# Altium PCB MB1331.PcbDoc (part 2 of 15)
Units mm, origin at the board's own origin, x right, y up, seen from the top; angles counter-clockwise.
Board outline 169.25 x 173.25 mm, 6 copper layers (Top Layer, Signal Layer 1, Signal Layer 2, Signal Layer 3, Signal Layer 4, Bottom Layer), stack 1.556 mm thick; 871 components, 699 nets, 3244 pads, 2370 vias.
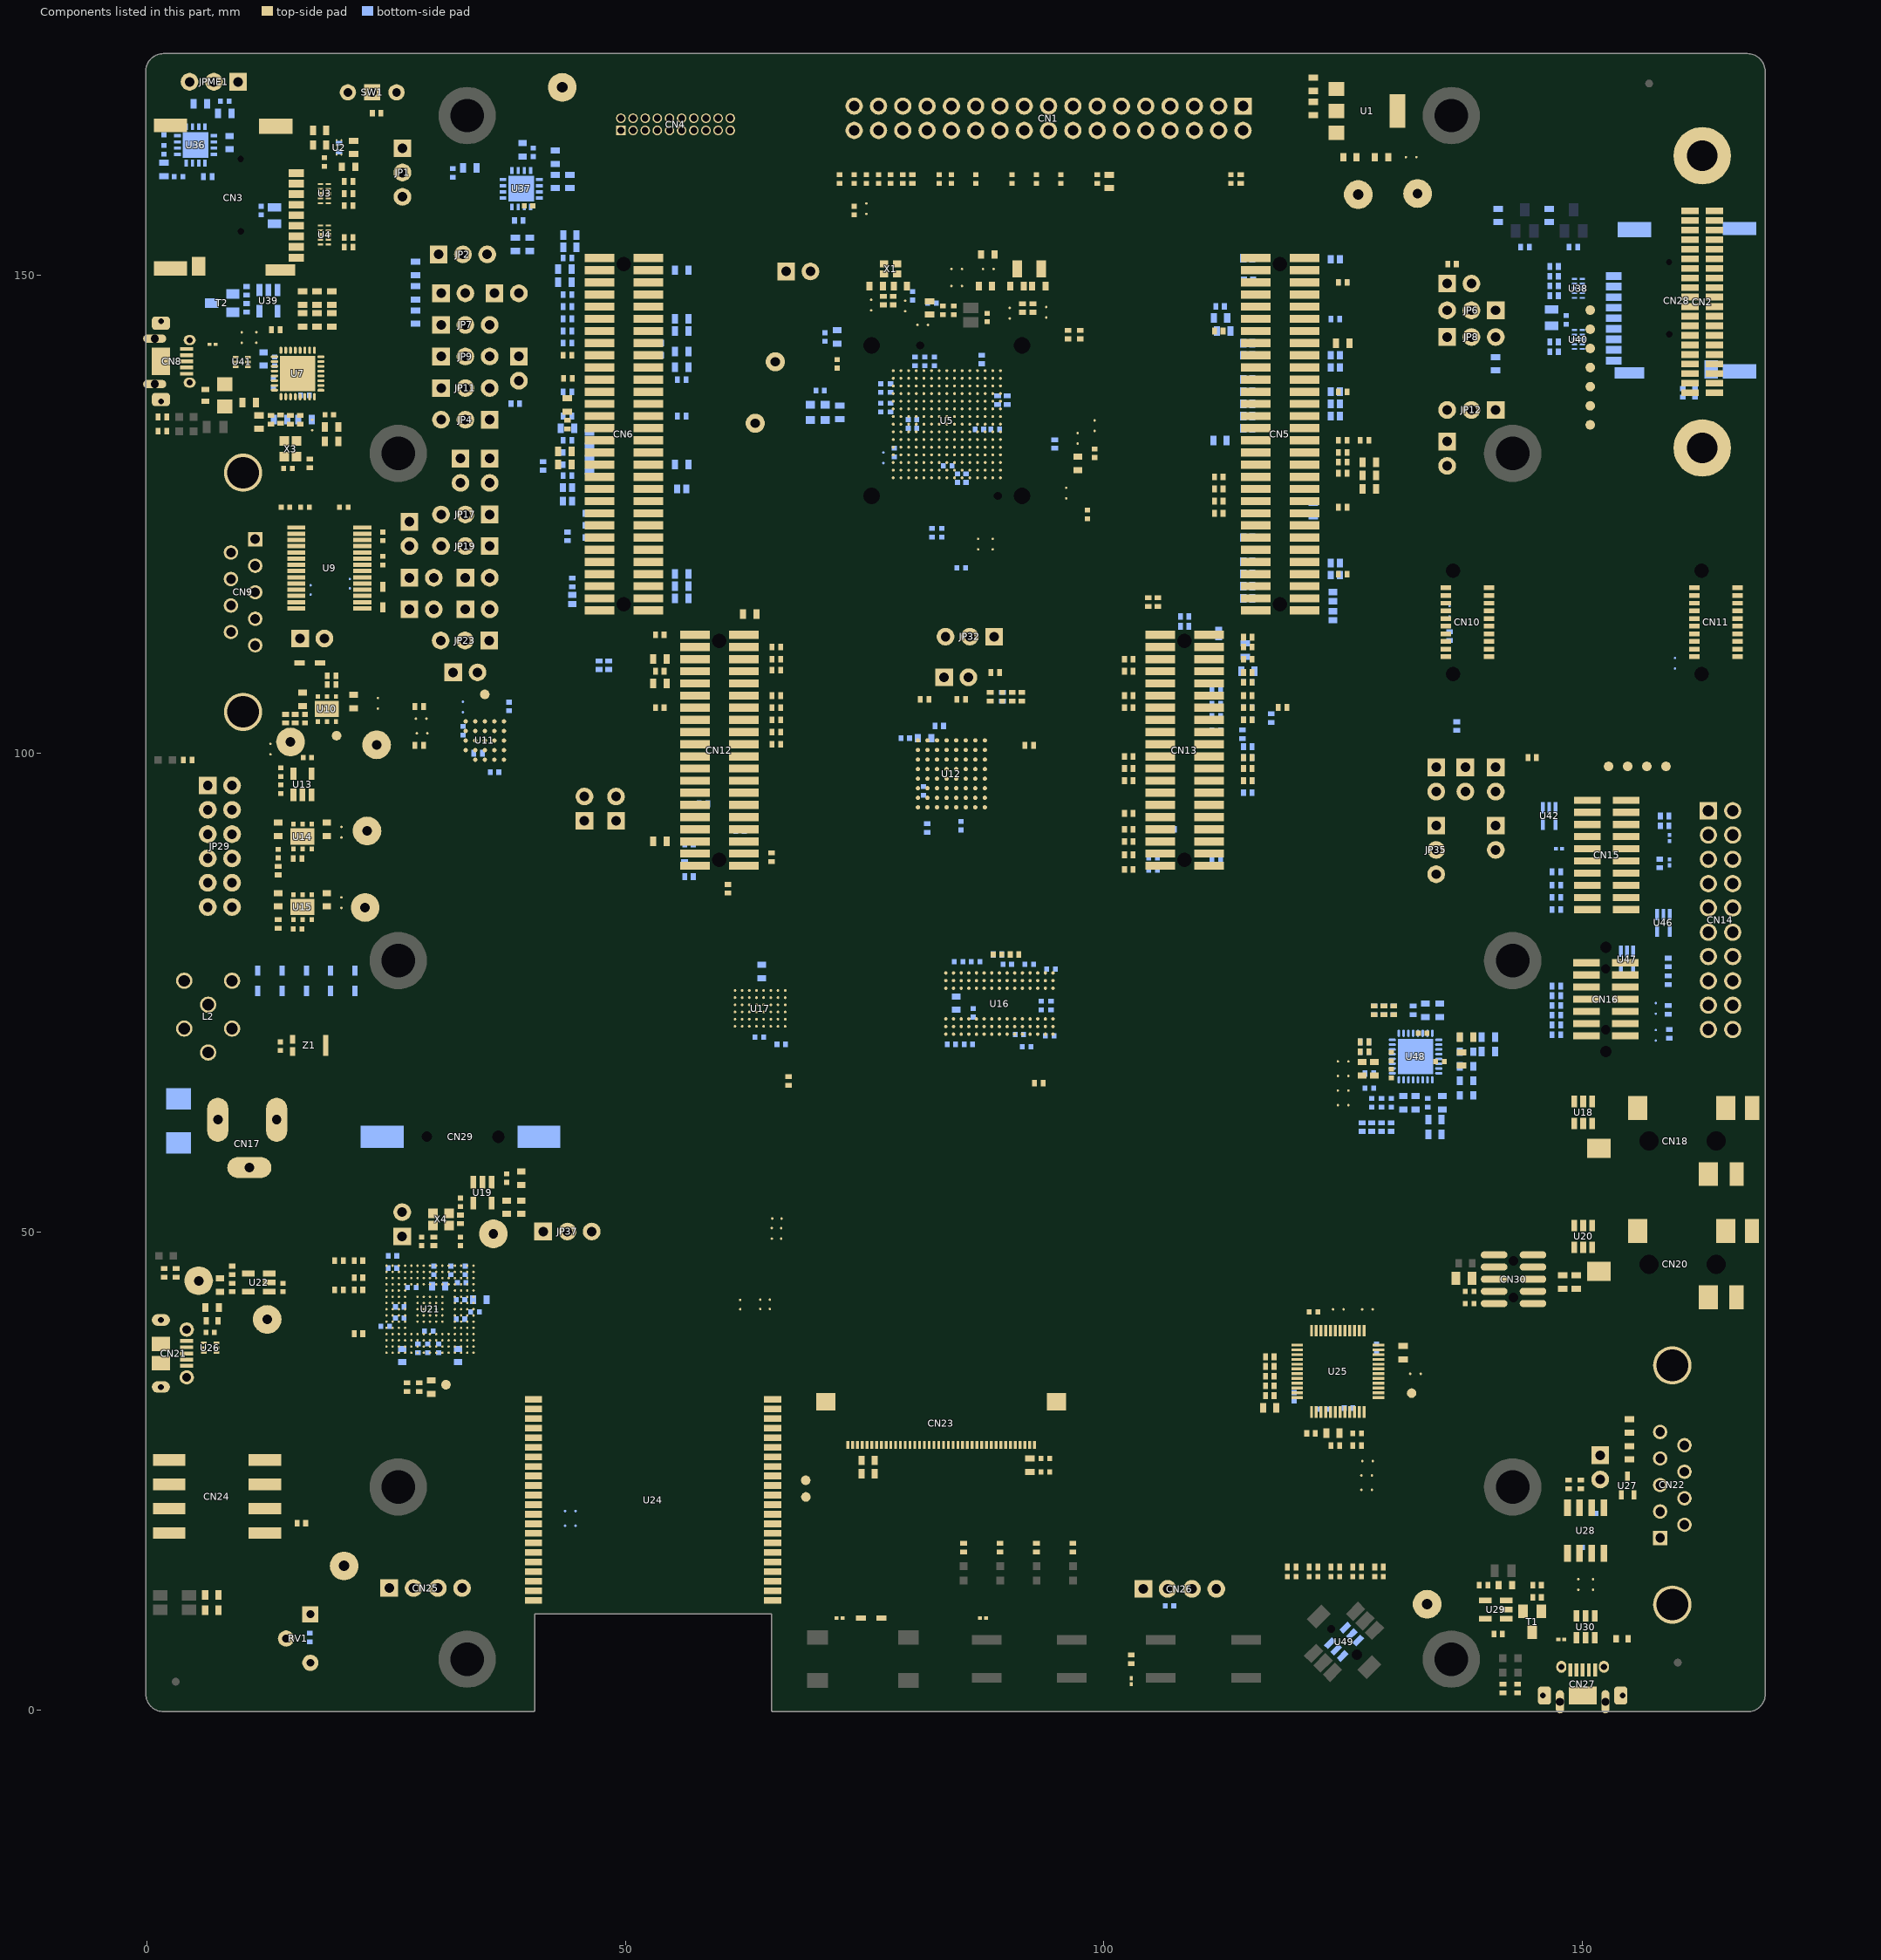
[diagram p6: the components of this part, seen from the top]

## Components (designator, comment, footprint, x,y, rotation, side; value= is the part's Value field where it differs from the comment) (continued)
R185 "Resistor" R0402 124.206,14.986 r0 top value=10K
R186 "Resistor" R0402 126.492,14.986 r180 top value=10K
R187 "Resistor" R0402 128.778,14.986 r0 top value=10K
R188 "Resistor" R0402 139.7,13.081 r0 top value=10K
R189 "Resistor" R0402 145.288,13.081 r0 top value=47K
R190 "Resistor" R0603 6.777,12.078 r0 top value=330R
R191 "Resistor" R0402 145.288,11.811 r0 top value=10K
R192 "Resistor" R0603 6.777,10.478 r0 top value=330R
R193 "Resistor" R0402 141.224,8.001 r180 top value=47K
R194 "Resistor" R0402 102.87,5.334 r90 top value=10K
R195 "Resistor" R0402 141.732,2.286 r270 top value=360R
R196 "Resistor" R0402 143.256,2.286 r270 top value=270R
R197 "Resistor" R0603 5.588,167.894 r180 bottom value=1K
R198 "Resistor" R0603 8.128,166.878 r180 bottom value=1K
R199 "Resistor" R0402 20.066,163.322 r270 bottom value=10K
R200 "PT100" R0603_H0P45 42.672,162.306 r270 bottom value="PTS 100R @ 0°C"
R201 "Resistor" R0603 33.738,161.163 r180 bottom value=0R
R202 "Resistor" R0603 1.778,161.036 r270 bottom value=0R
R203 "Resistor" R0603 44.196,159.766 r90 bottom value=3K3
R204 "Resistor" R0603 42.672,159.766 r270 bottom value=100R
R205 "Resistor" R0402 6.35,160.274 r0 bottom value=0R
R206 "Resistor" R0603 146.558,156.21 r270 bottom value=0R
R207 "Resistor" R0603 141.224,156.21 r270 bottom value=0R
R208 "Resistor" R0402 38.862,155.702 r0 bottom value=0R
R209 "Resistor" R0603 44.196,154.178 r180 bottom value=0R
R210 "Resistor" R0603 44.196,152.908 r180 bottom value=0R
R211 "Resistor" R0402 149.098,152.908 r0 bottom value=4K7
R212 "Resistor" R0402 144.018,152.908 r0 bottom value=4K7
R213 "Resistor" R0603 53.34,151.13 r270 bottom value=0R
R214 "Inductor" IND_0402_MURATA_BLM15H_H0P5 124.206,151.64 r0 bottom value="470ohms @ 100MHz"
R215 "Inductor" IND_0402_MURATA_BLM15H_H0P5 115.062,151.765 r0 bottom value="470ohms @ 100MHz"
R216 "Resistor" R0402 43.942,151.765 r0 bottom value=0R
R217 "Resistor" R0402 147.066,150.876 r180 bottom value=10K
R218 "Resistor" R0603 43.688,150.622 r0 bottom value=47R
R219 "Resistor" R0603 55.88,150.495 r180 bottom value=0R
R220 "Resistor" R0603 38.5,153.2 r270 bottom value=0R
R221 "Resistor" R0603 28.08,150.674 r270 bottom value=0R
R222 "Resistor" R0603 28.08,148.134 r270 bottom value=47R
R223 "Resistor" R0603 28.08,145.594 r270 bottom value=0R
R224 "Resistor" R0402 147.066,149.86 r180 bottom value=47K
R225 "Resistor" R0603 43.688,149.225 r0 bottom value=820R
R226 "Inductor" IND_0402_MURATA_BLM15H_H0P5 115.125,149.375 r0 bottom value="470ohms @ 100MHz"
R227 "Resistor" R0402 147.066,148.844 r180 bottom value=47K
R228 "Resistor" R0402 10.414,148.336 r270 bottom value=47K
R229 "Resistor" R0402 53.086,147.955 r0 bottom value=0R
R230 "Resistor" R0402 43.942,147.955 r180 bottom value=0R
R231 "Resistor" R0402 147.066,147.828 r180 bottom value=10K
R232 "Resistor" R0402 10.414,146.558 r90 bottom value=10K
R233 "Resistor" R0402 112.156,146.7 r180 bottom value=0R
R234 "Resistor" R0402 43.942,146.685 r180 bottom value=0R
R235 "Resistor" R0603 55.88,145.415 r180 bottom value=0R
R236 "Resistor" R0402 53.086,145.415 r0 bottom value=0R
R237 "Resistor" R0402 43.942,145.415 r180 bottom value=0R
R238 "Resistor" R0603 112.522,144.145 r0 bottom value=0R
R239 "Resistor" R0603 55.88,144.145 r180 bottom value=0R
R240 "Resistor" R0402 53.086,144.145 r0 bottom value=0R
R241 "Resistor" R0402 43.942,144.145 r180 bottom value=0R
R242 "Resistor" R0402 147.066,143.002 r180 bottom value=47K
R243 "Inductor" IND_0402_MURATA_BLM15H_H0P5 115.062,142.875 r0 bottom value="470ohms @ 100MHz"
R244 "Resistor" R0402 53.34,142.875 r0 bottom value=0R
R245 "Resistor" R0402 43.942,142.875 r0 bottom value=0R
R246 "Resistor" R0603 55.88,141.986 r180 bottom value=0R
R247 "Resistor" R0402 147.066,141.986 r180 bottom value=47K
R248 "Inductor" IND_0402_MURATA_BLM15H_H0P5 124.206,141.605 r0 bottom value="470ohms @ 100MHz"
R249 "Inductor" IND_0402_MURATA_BLM15H_H0P5 115.062,141.605 r0 bottom value="470ohms @ 100MHz"
R250 "Resistor" R0402 53.34,141.605 r0 bottom value=0R
R251 "Resistor" R0402 87.249,141.166 r270 bottom value=0R
R252 "Resistor" R0603 140.97,140.716 r90 bottom value=47R
R253 "Resistor" R0603 55.88,140.335 r180 bottom value=0R
R254 "Inductor" IND_0402_MURATA_BLM15H_H0P5 124.206,140.335 r0 bottom value="470ohms @ 100MHz"
R255 "Resistor" R0402 53.086,140.335 r0 bottom value=0R
R256 "Inductor" IND_0402_MURATA_BLM15H_H0P5 115.062,139.065 r0 bottom value="470ohms @ 100MHz"
R257 "Resistor" R0402 55.88,139.065 r180 bottom value=0R
R258 "Resistor" R0402 53.1,136.5 r180 bottom value=0R
R259 "Inductor" IND_0402_MURATA_BLM15H_H0P5 124.206,137.795 r0 bottom value="470ohms @ 100MHz"
R260 "Inductor" IND_0402_MURATA_BLM15H_H0P5 115.062,137.795 r0 bottom value="470ohms @ 100MHz"
R261 "Resistor" R0402 43.942,137.795 r0 bottom value=0R
R262 "Resistor" R0402 89.916,136.906 r90 bottom value=0R
R263 "Resistor" R0402 88.9,136.906 r90 bottom value=0R
R264 "Inductor" IND_0402_MURATA_BLM15H_H0P5 124.206,136.525 r0 bottom value="470ohms @ 100MHz"
R265 "Inductor" IND_0402_MURATA_BLM15H_H0P5 115.062,136.525 r0 bottom value="470ohms @ 100MHz"
R266 "Resistor" R0603 72.39,135.636 r90 bottom value=0R
R267 "BEAD" L0603 70.866,135.636 r270 bottom value=600R@100MHz
R268 "BEAD" L0603 69.342,135.636 r270 bottom value=600R@100MHz
R269 "Inductor" IND_0402_MURATA_BLM15H_H0P5 124.206,135.255 r0 bottom value="470ohms @ 100MHz"
R270 "Inductor" IND_0402_MURATA_BLM15H_H0P5 115.062,135.255 r0 bottom value="470ohms @ 100MHz"
R271 "Resistor" R0402 55.88,135.255 r180 bottom value=0R
R272 "Resistor" R0402 43.942,135.255 r0 bottom value=0R
R273 "Resistor" R0603 16.51,134.874 r180 bottom value=0R
R274 "Resistor" R0603 13.97,134.874 r0 bottom value=0R
R275 "Resistor" R0603 43.942,133.985 r0 bottom value=0R
R276 "Inductor" IND_0402_MURATA_BLM15H_H0P5 115.062,133.985 r0 bottom value="470ohms @ 100MHz"
R277 "Resistor" R0603 46.228,132.842 r270 bottom value=0R
R278 "Resistor" R0603 112.147,132.715 r0 bottom value=0R
R279 "Resistor" R0402 43.942,132.715 r0 bottom value=1K
R280 "Resistor" R0402 94.869,132.334 r90 bottom value=0R
R281 "Resistor" R0402 43.942,131.445 r0 bottom value=0R
R282 "Resistor" R0603 46.228,130.175 r270 bottom value=0R
R283 "Resistor" R0402 41.402,130.048 r90 bottom value=0R
R284 "Resistor" R0603 55.88,130.175 r180 bottom value=0R
R285 "Resistor" R0603 92.258,25.627 r90 top value=0R
R286 "Resistor" R0402 43.942,130.175 r0 bottom value=0R
R287 "Resistor" R0402 43.942,129.032 r180 bottom value=0R
R288 "Resistor" R0603 121.92,128.27 r270 bottom value=0R
R289 "Resistor" R0402 53.086,128.905 r180 bottom value=0R
R290 "Inductor" IND_0402_MURATA_BLM15H_H0P5 43.942,127.762 r180 bottom value="470ohms @ 100MHz"
R291 "Inductor" IND_0402_MURATA_BLM15H_H0P5 55.88,127.635 r0 bottom value="470ohms @ 100MHz"
R292 "Resistor" R0402 53.086,126.365 r0 bottom value=0R
R293 "Inductor" IND_0402_MURATA_BLM15H_H0P5 43.942,126.365 r180 bottom value="470ohms @ 100MHz"
R294 "Resistor" R0603 121.92,125.476 r90 bottom value=0R
R295 "Resistor" R0402 53.086,125.095 r0 bottom value=0R
R296 "Resistor" R0402 46.228,125.095 r180 bottom value=0R
R297 "Resistor" R0402 46.228,123.825 r0 bottom value=0R
R298 "Resistor" R0402 43.942,122.682 r270 bottom value=10K
R299 "Inductor" IND_0402_MURATA_BLM15H_H0P5 115.062,122.555 r0 bottom value="470ohms @ 100MHz"
R300 "Resistor" R0402 46.228,122.555 r180 bottom value=0R
R301 "Resistor" R0603 46.482,119.38 r270 bottom value=0R
R302 "Inductor" IND_0402_MURATA_BLM15H_H0P5 124.206,119.89 r0 bottom value="470ohms @ 100MHz"
R303 "Inductor" IND_0402_MURATA_BLM15H_H0P5 115.062,120.015 r0 bottom value="470ohms @ 100MHz"
R304 "Resistor" R0603 55.88,118.745 r180 bottom value=0R
R305 "Inductor" IND_0402_MURATA_BLM15H_H0P5 124.206,118.645 r0 bottom value="470ohms @ 100MHz"
R306 "Inductor" IND_0402_MURATA_BLM15H_H0P5 115.062,118.745 r0 bottom value="470ohms @ 100MHz"
R308 "Resistor" R0402 44.45,117.856 r90 bottom value=0R
R309 "Resistor" R0603 55.88,117.475 r180 bottom value=0R
R310 "Inductor" IND_0402_MURATA_BLM15H_H0P5 115.062,117.475 r0 bottom value="470ohms @ 100MHz"
R312 "Inductor" IND_0402_MURATA_BLM15H_H0P5 123.952,116.386 r270 bottom value="470ohms @ 100MHz"
R313 "Inductor" IND_0402_MURATA_BLM15H_H0P5 44.45,116.078 r270 bottom value="470ohms @ 100MHz"
R314 "Resistor" R0603 55.88,116.205 r180 bottom value=0R
R315 "Inductor" IND_0402_MURATA_BLM15H_H0P5 115.062,116.205 r0 bottom value="470ohms @ 100MHz"
R316 "Resistor" R0402 53.086,116.205 r0 bottom value=0R
R317 "Inductor" IND_0402_MURATA_BLM15H_H0P5 123.952,114.383 r270 bottom value="470ohms @ 100MHz"
R318 "Resistor" R0402 108.458,114.3 r180 bottom value=0R
R319 "Resistor" R0402 108.458,113.284 r180 bottom value=0R
R320 "Resistor" R0402 112.014,112.522 r90 bottom value=0R
R321 "Resistor" R0402 136.144,112.268 r90 bottom value=10K
R322 "Resistor" R0402 62.992,112.395 r0 bottom value=0R
R323 "Resistor" R0603 114.8,110.8 r270 bottom value=0R
R324 "Resistor" R0402 110.982,111.125 r180 bottom value=0R
R325 "Resistor" R0402 56.638,111.125 r0 bottom value=0R
R326 "Resistor" R0402 56.638,109.855 r0 bottom value=0R
R328 "Resistor" R0402 48.26,109.22 r270 bottom value=470R
R329 "Resistor" R0402 47.244,109.22 r270 bottom value=470R
R330 "Resistor" R0603 115.062,108.585 r180 bottom value=0R
R331 "Resistor" R0402 111.76,108.585 r180 bottom value=0R
R332 "Resistor" R0402 62.992,108.585 r180 bottom value=0R
R333 "Resistor" R0402 56.638,108.585 r180 bottom value=0R
R334 "Resistor" R0402 115.062,107.442 r180 bottom value=0R
R335 "Resistor" R0402 111.76,106.68 r180 bottom value=0R
R336 "Resistor" R0402 89.408,105.918 r270 bottom value=220K
R337 "Resistor" R0402 117.5,103.7 r90 bottom value=0R
R338 "Resistor" R0402 56.638,106.045 r0 bottom value=0R
R339 "Resistor" R0402 111.76,105.156 r180 bottom value=0R
R340 "Resistor" R0402 115.062,104.775 r180 bottom value=0R
R341 "Resistor" R0402 56.638,104.775 r0 bottom value=0R
R342 "Resistor" R0402 111.76,103.886 r180 bottom value=0R
R343 "Resistor" R0402 115.062,103.505 r180 bottom value=0R
R344 "Resistor" R0402 105.156,103.505 r0 bottom value=0R
R345 "Resistor" R0402 56.638,103.505 r0 bottom value=0R
R346 "Resistor" R0402 82.804,102.87 r0 bottom value=220K
R347 "Resistor" R0402 111.76,102.362 r0 bottom value=0R
R348 "Resistor" R0402 56.638,102.235 r0 bottom value=0R
R349 "Resistor" R0402 124.2,145.4 r180 bottom value=0R
R350 "Resistor" R0402 114.5,102 r270 bottom value=0R
R351 "Resistor" R0402 111.76,100.965 r180 bottom value=0R
R352 "Resistor" R0402 105.156,100.965 r180 bottom value=0R
R353 "Resistor" R0402 56.638,100.965 r0 bottom value=0R
R354 "Resistor" R0402 115.062,100.711 r180 bottom value=0R
R355 "Resistor" R0402 34.613,100.018 r0 bottom value=10K
R356 "Resistor" R0402 111.76,99.695 r0 bottom value=0R
R357 "Resistor" R0402 105.156,99.695 r0 bottom value=0R
R358 "Resistor" R0402 62.992,99.695 r0 bottom value=0R
R359 "Resistor" R0402 56.638,99.695 r0 bottom value=0R
R360 "Resistor" R0402 115.062,99.568 r180 bottom value=0R
R361 "Resistor" R0402 62.992,98.425 r0 bottom value=0R
R362 "Resistor" R0402 56.638,98.425 r0 bottom value=0R
R363 "Resistor" R0402 115.062,97.155 r180 bottom value=0R
R364 "Resistor" R0402 111.76,97.155 r180 bottom value=0R
R365 "Resistor" R0402 62.992,97.155 r0 bottom value=0R
R366 "Resistor" R0402 56.638,97.155 r180 bottom value=0R
R367 "Resistor" R0402 115.062,95.885 r180 bottom value=0R
R368 "Resistor" R0402 111.76,95.885 r180 bottom value=0R
R369 "Resistor" R0402 62.992,95.885 r0 bottom value=0R
R370 "Resistor" R0402 56.638,95.885 r180 bottom value=0R
R371 "Resistor" R0402 58.166,94.742 r0 bottom value=0R
R372 "Resistor" R0402 158.628,93.453 r0 bottom value=0R
R373 "Resistor" R0402 111.76,93.345 r180 bottom value=0R
R374 "Resistor" R0402 61.976,93.345 r0 bottom value=0R
R375 "Resistor" R0402 56.638,93.345 r0 bottom value=0R
R376 "Resistor" R0402 81.534,92.202 r270 bottom value=10K
R377 "Resistor" R0402 158.628,92.437 r180 bottom value=1K
R378 "Resistor" R0402 106.934,92.075 r180 bottom value=0R
R380 "Resistor" R0402 56.638,92.075 r180 bottom value=0R
R381 "Resistor" R0402 61.976,91.948 r180 bottom value=0R
R382 "Resistor" R0402 111.76,90.805 r0 bottom value=0R
R384 "Resistor" R0402 56.642,90.551 r0 bottom value=0R
R385 "Resistor" R0402 56.188,89.154 r270 bottom value=0R
R386 "Resistor" R0402 105.156,89.154 r180 bottom value=0R
R387 "Resistor" R0402 111.76,88.9 r0 bottom value=0R
R388 "Resistor" R0402 158.12,88.5 r270 bottom value=1K
R389 "Resistor" R0402 105.156,87.884 r180 bottom value=0R
R390 "Resistor" R0402 147.32,87.63 r0 bottom value=0R
R391 "Resistor" R0402 56.642,87.122 r180 bottom value=0R
R392 "Resistor" R0402 147.32,86.233 r180 bottom value=1K
R393 "Resistor" R0402 147.32,84.963 r0 bottom value=1K
R394 "Resistor" R0402 147.32,83.693 r180 bottom value=1K
R395 "Resistor" R0402 159,78.15 r270 bottom value=10K
R396 "Resistor" R0402 159,76.3 r270 bottom value=1K
R397 "Resistor" R0402 88.9,78.994 r180 bottom value=0R
R398 "Resistor" R0402 147.32,75.692 r0 bottom value=0R
R399 "Resistor" R0402 147.32,74.676 r0 bottom value=0R
R400 "Resistor" R0402 159,73.2 r270 bottom value=10K
R401 "Resistor" R0402 147.32,73.66 r0 bottom value=0R
R402 "Resistor" R0402 132.334,73.152 r90 bottom value=10K
R403 "Resistor" R0402 130.302,73.152 r90 bottom value=0R
R404 "Resistor" R0402 129.286,73.152 r90 bottom value=0R
R405 "Resistor" R0402 128.27,73.152 r90 bottom value=0R
R406 "Resistor" R0402 147.32,72.644 r180 bottom value=0R
R407 "Resistor" R0402 147.32,71.628 r180 bottom value=0R
R408 "Resistor" R0402 159.1,70.7 r90 bottom value=10K
R409 "Resistor" R0402 147.32,70.612 r0 bottom value=0R
R410 "Resistor" R0603 140.208,70.358 r180 bottom value=49.9R
R411 "Resistor" R0402 127.254,69.85 r180 bottom value=0R
R412 "Resistor" R0603 140.208,68.834 r180 bottom value=49.9R
R413 "Resistor" R0402 127.254,68.834 r180 bottom value=0R
R414 "Resistor" R0402 127.762,66.548 r0 bottom value=10K
R415 "Resistor" R0603 134.62,61.722 r180 bottom value=2K2
R416 "Resistor" R0402 130.048,60.96 r270 bottom value=100K
R417 "Resistor" R0402 129.032,60.96 r90 bottom value=100R
R418 "Resistor" R0402 128.016,60.96 r90 bottom value=100R
R419 "Resistor" R0402 127,60.96 r90 bottom value=100K
R420 "Resistor" R0603 134.62,60.198 r0 bottom value=100K
RV1 "POTENTIOMETER" POT_BOURNS_3386P 17.055,7.51 r270 top value=10K
SB1 "SB_ON" SOLDER-BRIDGE_R0603-0R 132.08,162.306 r0 top
SB2 "SB_ON" SOLDER-BRIDGE_R0603-0R 75.184,156.972 r270 top
SB3 "SB_ON" SOLDER-BRIDGE_R0603-0R 84.582,150.622 r0 top
SB4 "SB_ON" SOLDER-BRIDGE_R0603-0R 87.884,150.622 r0 top
SB5 "SB_ON" SOLDER-BRIDGE_R0603-0R 84.582,148.844 r0 top
SB6 "SB_ON" SOLDER-BRIDGE_R0603-0R 75.692,146.812 r90 top
SB7 "SB_ON" SOLDER-BRIDGE_R0603-0R 79.248,146.812 r270 top
SB8 "SB_ON" SOLDER-BRIDGE_R0603-0R 90.17,146.05 r270 top
SB9 "SB_ON" SOLDER-BRIDGE_R0603-0R 93.98,146.05 r90 top
SB10 "SB_ON" SOLDER-BRIDGE_R0603-0R 81.026,144.78 r0 top
SB11 "SB_ON" SOLDER-BRIDGE_R0603-0R 9.906,143.51 r270 top
SB12 "SB_ON" SOLDER-BRIDGE_R0603-0R 11.43,143.51 r270 top
SB13 "SB_ON" SOLDER-BRIDGE_R0603-0R 17.272,134.366 r270 top
SB14 "SB_ON" SOLDER-BRIDGE_R0603-0R 99.05,134.3 r270 top
SB15 "SB_ON" SOLDER-BRIDGE_R0603-0R 97.275,132.975 r270 top
SB16 "SB_ON" SOLDER-BRIDGE_R0603-0R 96.075,127.15 r90 top
SB17 "SB_ON" SOLDER-BRIDGE_R0603-0R 86.868,121.92 r270 top
SB18 "SB_ON" SOLDER-BRIDGE_R0603-0R 88.392,121.92 r270 top
SB19 "SB_ON" SOLDER-BRIDGE_R0603-0R 24.13,105.283 r270 top
SB20 "SB_ON" SOLDER-BRIDGE_R0603-0R 28.702,103.632 r180 top
SB21 "SB_ON" SOLDER-BRIDGE_R0603-0R 28.702,102.108 r0 top
SB22 "SB_ON" SOLDER-BRIDGE_R0603-0R 12.9,100.4 r90 top
SB23 "SB_ON" SOLDER-BRIDGE_R0603-0R 20.32,91.821 r270 top
SB24 "SB_ON" SOLDER-BRIDGE_R0603-0R 20.32,84.455 r270 top
SB25 "SB_ON" SOLDER-BRIDGE_R0603-0R 124.968,67.818 r0 top
SB26 "SB_ON" SOLDER-BRIDGE_R0603-0R 124.968,66.294 r0 top
SB27 "SB_ON" SOLDER-BRIDGE_R0603-0R 124.968,64.77 r0 top
SB28 "SB_ON" SOLDER-BRIDGE_R0603-0R 124.968,63.246 r0 top
SB29 "SB_ON" SOLDER-BRIDGE_R0603-0R 124.46,41.91 r0 top
SB30 "SB_ON" SOLDER-BRIDGE_R0603-0R 127.508,41.91 r0 top
SB31 "SB_ON" SOLDER-BRIDGE_R0603-0R 127.525,24.55 r180 top
SB32 "SB_ON" SOLDER-BRIDGE_R0603-0R 127.525,23.05 r180 top
SB33 "SB_ON" SOLDER-BRIDGE_R0603-0R 127.525,26.05 r0 top
SB34 "SB_ON" SOLDER-BRIDGE_R0603-0R 132.625,35.175 r180 top
SB35 "SB_ON" SOLDER-BRIDGE_R0603-0R 149.606,13.208 r270 top
SB36 "SB_ON" SOLDER-BRIDGE_R0603-0R 151.13,13.208 r270 top
SB37 "SB_ON" SOLDER-BRIDGE_R0603-0R 76.962,130.937 r270 bottom
SB38 "SB_ON" SOLDER-BRIDGE_R0603-0R 136.144,114.808 r90 bottom
SB39 "SB_ON" SOLDER-BRIDGE_R0603-0R 159.702,109.474 r270 bottom
SB40 "SB_ON" SOLDER-BRIDGE_R0603-0R 33.02,104.902 r270 bottom
SB41 "SB_ON" SOLDER-BRIDGE_R0402-0R 65.75,50.4 r0 top
SB42 "SB_ON" SOLDER-BRIDGE_R0402-0R 64.1,42.4 r90 top
SB43 "SB_ON" SOLDER-BRIDGE_R0603-0R 157.7,73.3 r90 bottom
SB44 "SB_ON" SOLDER-BRIDGE_R0603-0R 157.7,70.6 r270 bottom
SB45 "SB_ON" SOLDER-BRIDGE_R0603-0R 44.196,20.828 r0 bottom
SB46 "SB_ON" SOLDER-BRIDGE_R0603-0R 44.196,19.304 r0 bottom
SB47 "SB_ON" SOLDER-BRIDGE_R0402-0R 65.1,42.4 r90 top
SB48 "SB_ON" SOLDER-BRIDGE_R0402-0R 65.75,49.3 r0 top
SB49 "SB_ON" SOLDER-BRIDGE_R0402-0R 21.2,117.7 r90 bottom
SB50 "SB_ON" SOLDER-BRIDGE_R0402-0R 17.1,117.05 r90 bottom
SB51 "SB_ON" SOLDER-BRIDGE_R0402-0R 62,42.45 r270 top
SB52 "SB_ON" SOLDER-BRIDGE_R0402-0R 65.8,51.4 r0 top
SW1 "SW_MECA_1K2" SWI_EAO_09-03290-01_EXTENDED_STRAIGHT_BLACK 23.538,169.075 r270 top value="Mechanical Slide Switch 1K2"
T1 "9013-SOT23" NPN_SOT23 144.78,9.271 r180 top value="NPN SOT23"
T2 "9013-SOT23" NPN_SOT23 7.874,147.066 r270 bottom value="NPN SOT23"
TP1 "Test_pin_conn_red" TP_PTH-1MM_TEST-TERMINAL_RS_262-2185_RED 132.8,158.5 r0 top value=TP
TP2 "Test Point" TP_SMD_1MM 150.846,146.327 r0 top
TP3 "Test Point" TP_SMD_1MM 150.846,144.327 r0 top
TP4 "Test Point" TP_SMD_1MM 150.846,142.327 r0 top
TP5 "Test Point" TP_SMD_1MM 150.846,140.327 r0 top
TP6 "Test Point" TP_SMD_1MM 150.846,138.327 r0 top
TP7 "Test Point" TP_SMD_1MM 150.846,136.327 r0 top
TP8 "Test Point" TP_SMD_1MM 150.846,134.327 r0 top
TP9 "Test Point" TP_SMD_1MM 35.306,106.172 r90 top
TP10 "Test_pin_conn_red" TP_PTH-1MM_TEST-TERMINAL_RS_262-2185_RED 24,100.9 r90 top value=TP
TP11 "Test Point" TP_SMD_1MM 19.812,101.854 r90 top
TP12 "Test_pin_conn_red" TP_PTH-1MM_TEST-TERMINAL_RS_262-2185_RED 15,101.2 r270 top value=TP
TP13 "Test Point" TP_SMD_1MM 152.76,98.645 r0 top
TP14 "Test Point" TP_SMD_1MM 154.76,98.645 r0 top
TP15 "Test Point" TP_SMD_1MM 156.76,98.645 r270 top
TP16 "Test Point" TP_SMD_1MM 158.76,98.645 r0 top
TP17 "Test_pin_conn_red" TP_PTH-1MM_TEST-TERMINAL_RS_262-2185_RED 23,91.9 r270 top value=TP
TP18 "Test_pin_conn_red" TP_PTH-1MM_TEST-TERMINAL_RS_262-2185_RED 22.8,83.9 r90 top value=TP
TP19 "Test_pin_conn_red" TP_PTH-1MM_TEST-TERMINAL_RS_262-2185_RED 36.2,49.8 r180 top value=TP
TP20 "Test_pin_conn_red" TP_PTH-1MM_TEST-TERMINAL_RS_262-2185_RED 5.4,44.9 r90 top value=TP
TP21 "Test_pin_conn_red" TP_PTH-1MM_TEST-TERMINAL_RS_262-2185_RED 12.562,40.859 r90 top value=TP
TP22 "Test Point" TP_SMD_1MM 31.242,34.036 r90 top
TP23 "Test Point" TP_SMD_1MM 132.175,33.15 r90 top
TP24 "Test_Point_PTH_1mm_2mm" TP_PTH_1MM_2MM 65.675,140.925 r180 top value=TP
TP25 "Test_Point_PTH_1mm_2mm" TP_PTH_1MM_2MM 63.575,134.5 r180 top value=TP
TP26 "Test Point" TP_SMD_1MM 68.868,22.304 r90 top
TP27 "Test Point" TP_SMD_1MM 68.841,24.048 r90 top
TPG1 "Test_pin_conn_black" TP_PTH-1P02MM_TEST-TERMINAL_RS_101-2391_BLACK 43.4,169.6 r0 top value=TP
TPG2 "Test_pin_conn_black" TP_PTH-1P02MM_TEST-TERMINAL_RS_101-2391_BLACK 126.6,158.4 r90 top value=TP
TPG3 "Test_pin_conn_black" TP_PTH-1P02MM_TEST-TERMINAL_RS_101-2391_BLACK 133.8,11.1 r90 top value=TP
TPG4 "Test_pin_conn_black" TP_PTH-1P02MM_TEST-TERMINAL_RS_101-2391_BLACK 20.6,15.1 r90 top value=TP
U1 "LD1117STR" REG_SOT223-TAB 127.508,167.132 r270 top
U2 "STG4160" ESD_FLIP-CHIP-BGA8_1P9X0P9_P050 20.066,163.322 r270 top
U3 "HSP051-4M10" ESD_UQFN-10L_2P5X1_P050 18.542,158.496 r90 top
U4 "HSP051-4M10" ESD_UQFN-10L_2P5X1_P050 18.542,154.178 r90 top
U5 "STM32H7B3NIH6Q" ICC_TFBGA225_13X13_STM32H7B3NIH6Q_P080__SOCKET_IRONWOOD_CS1222291MF_REV-A_WITHOUT-3D-SOCKET 83.6,134.4 r270 top locked value=STM32H7B3LIH6QU
U6 "ESD-TRANSIL" ESD_ST0201 6.858,142.748 r0 top value=ESDALC6V1-1U2
U7 "USB3320C-EZK" ICC_QFN32-EPAD_5X5_P050 15.748,139.7 r90 top
U8 "ESD-TRANSIL" ESD_QFN2_1P6X1_P125 6.096,137.414 r90 top value=ESDA7P60-1U1M
U9 "ST3241EBPR" ICC_SSOP28_10P2X5P3_P065 19.05,119.38 r270 top
U10 "ST1L05BPUR" ICC_DFN6-EPAD_3X3_P095 18.796,104.648 r0 top
U11 "MX25LM51245GXDI00" ICC_BGA24_5X5-BALL-ARRAY_6X8_P1 35.306,101.346 r90 top
U12 "PC28F128M29EWLA" ICC_FBGA64_11X13_P1 84.074,97.866 r270 top value=MT28EW128ABA1LPC-0SIT
U13 "LD3985M18R" REG_SOT23-5L 16.256,96.774 r0 top
U14 "ST1L05CPU33R" ICC_DFN6-EPAD_3X3_P095 16.256,91.313 r0 top value="ST1L05CPU33R 3.3V 1.3A"
U15 "ST1L05CPU33R" ICC_DFN6-EPAD_3X3_P095 16.256,83.947 r0 top value="ST1L05CPU33R 3.3V 1.3A"
U16 "IS42S32800G-6BLI" ICC_TFBGA90_8X13_P080 89.097,73.863 r270 top value=IS42S32800J-6BLI
U17 "IS61WV102416BLL-10MLI" ICC_MINI-BGA48_9X11_P075 64.078,73.355 r270 top locked
U18 "ESDA6V1BC6" ESD_SOT23-6L 150.114,62.484 r0 top
U19 "LD3985M33R" REG_SOT23-5L 35.052,54.102 r180 top
U20 "ESDA6V1BC6" ESD_SOT23-6L 150.114,49.53 r0 top
U21 "ST-LINKV3E_SWD" ICC_UFBGA201_176+25_10X10_P065 29.575,41.925 r270 top
U22 "STMPS2151STR" MOS_SOT23-5L 11.684,44.704 r90 top
U23 "ESD-TRANSIL" ESD_QFN2_1P6X1_P125 6.8,40.7 r0 top value=ESDA7P60-1U1M
U24 "WIFI MODULE INTERPOSER" MOD_WIFI_INVENTEK_ISM43362 52.9,20.2 r180 top locked value="MB1486 - WIFI MODULE WITH INVENTEK ISM43362-M3G-L44"
U25 "STM32L152CCT6" ICC_LQFP48_7X7_P050 124.46,35.433 r0 top
U26 "ECMF02-2AMX6" ESD_QFN-6L_1P7X1P5_P050 6.6,37.9 r90 top
U27 "ESD-TRANSIL-DUAL-BIDIR" DIO_SOT323 154.75,23.5 r0 top value=ESDCAN05-2BWY
U28 "MCP2562FD" ICC_SO8_5X4_P127 150.368,18.796 r0 top value=MCP2562FDT-H/SN
U29 "STMPS2151STR" MOS_SOT23-5L 140.97,10.541 r90 top
U30 "USBLC6-2SC6" ESD_SOT23-6L 150.368,8.738 r180 top
U31 "ESD-TRANSIL" ESD_ST0201 72.39,9.652 r180 top value=ESDALC6V1-1U2
U32 "ESD-TRANSIL" ESD_ST0201 87.376,9.652 r180 top value=ESDALC6V1-1U2
U33 "ESD-TRANSIL" ESD_QFN2_1P6X1_P125 154.178,7.493 r0 top value=ESDA7P60-1U1M
U34 "ESD-TRANSIL" ESD_ST0201 147.828,7.417 r0 top value=ESDALC6V1-1U2
U35 "ESD-TRANSIL" ESD_ST0201 102.87,3.048 r270 top value=ESDALC6V1-1U2
U36 "STPMS2L-PUR" ICC_QFN16-EPAD_4X4_P065 5.08,163.576 r90 bottom
U37 "STPMS2L-PUR" ICC_QFN16-EPAD_4X4_P065 39.116,159.004 r0 bottom
U38 "HSP051-4M10" ESD_UQFN-10L_2P5X1_P050 149.606,148.59 r90 bottom
U39 "STMPS2151STR" MOS_SOT23-5L 12.7,147.32 r0 bottom
U40 "HSP051-4M10" ESD_UQFN-10L_2P5X1_P050 149.606,143.256 r90 bottom
U41 "ECMF02-2AMX6" ESD_QFN-6L_1P7X1P5_P050 9.906,140.912 r90 top
U42 "ESDALC6V1W5" ESD_SOT323-5L 146.558,93.472 r0 bottom
U43 "ESD-TRANSIL" ESD_ST0201 159.136,91.167 r270 bottom value=ESDALC6V1-1U2
U44 "ESD-TRANSIL" ESD_ST0201 147.574,90.043 r180 bottom value=ESDALC6V1-1U2
U45 "ESD-TRANSIL" ESD_ST0201 159.136,88.627 r270 bottom value=ESDALC6V1-1U2
U46 "ESDALC6V1W5" ESD_SOT323-5L 158.496,82.296 r0 bottom
U47 "ESDALC6V1W5" ESD_SOT323-5L 154.686,78.486 r0 bottom
U48 "CS42L51-CNZ" ICC_QFN32-EPAD_5X5_P050 132.588,68.326 r0 bottom
U49 "ESDA6V1-5SC6" ESD_SOT23-6L 125.111,7.166 r315 bottom
X1 "XTAL_4_PINS" CRY_NX2016SA_4P 77.724,150.622 r180 top value="NX2016SA 24MHz"
X2 "XTAL_2_PINS" CRY_NX3215SA_2P 92.202,150.622 r180 top value="NX3215SA 32.768KHz"
X3 "OSCILLATOR_4_PINS" OSC_NDK_NZ2520SB_4P 14.986,131.826 r90 top value="NZ2520SB 24MHz"
X4 "OSCILLATOR_4_PINS" OSC_NDK_NZ2520SB_4P 30.734,51.308 r180 top value="NZ2520SH 25MHz"
Z1 "ZEN056V130A24LS" DIOZ_LITTELFUSE_ZEN056V130A24LS 16.949,69.493 r180 top

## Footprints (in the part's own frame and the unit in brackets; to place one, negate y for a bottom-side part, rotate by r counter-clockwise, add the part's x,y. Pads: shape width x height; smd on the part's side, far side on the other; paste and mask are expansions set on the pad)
BAT_HARWIN_S8411-45R_SMD_2P [mm] "CR1220 HOLDER"
  rect 4.5x2.3 smd mask+0.05: 1(8.2,0) 2(-8.2,0)
  round 0 hole 1.1 unplated mask+0.05: NPTH1(-3.5,0)
  round 0 hole 1.3 unplated mask+0.05: NPTH2(3.95,0)
  silkscreen extent -9.03,-7.5 9.62,7.5, body extent -8.93,-7.5 9.88,7.5, height 4.3
C0402 [mm]
  rect 0.51x0.56 smd mask+0.05: 1(-0.45,0) 2(0.45,0)
  silkscreen extent 0,-0.3 0,0.3, body extent -0.5,-0.3 0.5,0.3, height 0.4
C0603 [mm]
  rect 0.64x0.89 smd mask+0.05: 1(-0.7,0) 2(0.7,0)
  silkscreen extent -0.9,-0.55 1.05,0.55, body extent -0.9,-0.5 0.9,0.5, height 1.4
C0805 [mm]
  rect 0.9x1.4 smd mask+0.05: 1(-0.85,0) 2(0.85,0)
  silkscreen extent -1.3,-0.77 1.3,0.77, body extent -1.1,-0.7 1.1,0.7, height 1.35
CON_CVILUX_CH87-20-2-V-1-00 [mm]
  rect 1.8x1.8 hole 1.2 mask+0.05: 1(-11.43,-1.27)
  round 1.8 hole 1.2 mask+0.05: 2(-11.43,1.27) 3(-8.89,-1.27) 4(-8.89,1.27) 5(-6.35,-1.27) 6(-6.35,1.27) 7(-3.81,-1.27) 8(-3.81,1.27) 9(-1.27,-1.27) 10(-1.27,1.27) 11(1.27,-1.27) 12(1.27,1.27) 13(3.81,-1.27) 14(3.81,1.27) 15(6.35,-1.27) 16(6.35,1.27) 17(8.89,-1.27) 18(8.89,1.27) 19(11.43,-1.27) 20(11.43,1.27)
  silkscreen extent -16.51,-4.55 16.51,4.55, body extent -16.51,-4.57 16.51,4.57, height 9.86
CON_DB9-MALE_TYCO_2301843-2 [mm] "MCD-00127"
  rect 1.5x1.5 / inner round 1.5 / far side rect 1.5x1.5 hole 1 mask+0.05: 1(-5.54,8.77)
  round 1.5 hole 1 mask+0.05: 2(-2.77,8.77) 3(0,8.77) 4(2.77,8.77) 5(5.54,8.77) 6(-4.155,6.23) 7(-1.385,6.23) 8(1.385,6.23) 9(4.155,6.23)
  round 4 hole 3.3 mask+0.05: MT1(-12.5,7.5) MT2(12.5,7.5)
  silkscreen extent -15.5,-10.3 15.5,10.6, body extent -15.5,-10.3 15.5,10.6, height 13.8
CON_DC-POWER-SOCKET_CLIFF_FC68149_DC10B [mm]
  oval 2.2x4.6 hole 1 slot 3.5 at 90 deg mask+0.05: 1(-13.55,0) 3(-7.4,0)
  oval 4.6x2.2 hole 1 slot 3.5 at 0 deg mask+0.05: 2(-10.7,5)
  silkscreen extent -14.2,-4.6 0,4.6, body extent -14.3,-4.6 0.2,5.27, height 11
CON_FCI_20021311-XXX20XXLF [mm]
  rect 1x1 / inner round 1 / far side rect 1x1 hole 0.7 mask+0.05: 1(5.715,0.635)
  round 1 hole 0.7 mask+0.05: 2(5.715,-0.635) 3(4.445,0.635) 4(4.445,-0.635) 5(3.175,0.635) 6(3.175,-0.635) 7(1.905,0.635) 8(1.905,-0.635) 9(0.635,0.635) 10(0.635,-0.635) 11(-0.635,0.635) 12(-0.635,-0.635) 13(-1.905,0.635) 14(-1.905,-0.635) 15(-3.175,0.635) 16(-3.175,-0.635) 17(-4.445,0.635) 18(-4.445,-0.635) 19(-5.715,0.635) 20(-5.715,-0.635)
  silkscreen extent -6.58,-1.5 6.58,1.5, body extent -6.58,-1.5 6.58,1.5, height 4.4
CON_HRS_FH52E-40S-05SH [mm] "MCD-01992"
  rect 0.3x0.85 smd mask+0.05: 1(-9.75,2.263) 2(-9.25,2.263) 3(-8.75,2.263) 4(-8.25,2.263) 5(-7.75,2.263) 6(-7.25,2.263) 7(-6.75,2.263) 8(-6.25,2.263) 9(-5.75,2.263) 10(-5.25,2.263) 11(-4.75,2.263) 12(-4.25,2.263) 13(-3.75,2.263) 14(-3.25,2.263) 15(-2.75,2.263) 16(-2.25,2.263) 17(-1.75,2.263) 18(-1.25,2.263) 19(-0.75,2.263) 20(-0.25,2.263) 21(0.25,2.263) 22(0.75,2.263) 23(1.25,2.263) 24(1.75,2.263) 25(2.25,2.263) 26(2.75,2.263) 27(3.25,2.263) 28(3.75,2.263) 29(4.25,2.263) 30(4.75,2.263) 31(5.25,2.263) 32(5.75,2.263) 33(6.25,2.263) 34(6.75,2.263) 35(7.25,2.263) 36(7.75,2.263) 37(8.25,2.263) 38(8.75,2.263) 39(9.25,2.263) 40(9.75,2.263)
  rect 2x1.8 smd mask+0.05: MT1(-12.05,-2.262) MT2(12.05,-2.262)
  Top Layer keep-out region: -10.5,-9.662 10.5,-9.662 10.5,-3.412 -10.5,-3.412
  silkscreen extent -12.23,-9.41 12.22,1.59, body extent -12.65,-9.41 12.65,2.4, height 4.1
CON_MICROSD_YAMAICHI_PJS008-2003-1 [mm] "WITH POSITIONNING PINS"
  rect 1.6x0.8 smd paste+0 mask+0.05: 1(-15.6,-2.525) 2(-15.6,-1.425) 3(-15.6,-0.325) 4(-15.6,0.775) 5(-15.6,1.875) 6(-15.6,2.975) 7(-15.6,4.075) 8(-15.6,5.175) 9(-15.6,6.325)
  rect 1.4x1.95 smd paste+0 mask+0.05: 10(-5.4,7.225)
  rect 3.5x1.5 smd paste+0 mask+0.05: 11(-2.45,7.45)
  rect 3.5x1.4 smd paste+0 mask+0.05: 12(-2.45,-7.5)
  rect 3.5x1.6 smd paste+0 mask+0.05: 13(-13.45,-7.4)
  rect 3.1x1.2 smd paste+0 mask+0.05: 14(-13.95,7.6)
  round 0 hole 0.65 unplated mask+0.05: NPTH1(-9.8,-4)
  round 0 hole 0.7 unplated mask+0.05: NPTH2(-9.8,3.55)
  silkscreen extent -15.32,-7.25 5.65,7.25, body extent -15.25,-7.25 -0.45,7.42, height 2
CON_PHONE-JACK-3P5_HY_PJ3028B [mm]
  rect 1.5x2.5 smd mask+0.05: 2(1.25,-3.45) 7(2.85,3.45)
  rect 2x2.5 smd mask+0.05: 3(4,-3.45) 4(5.8,3.45) 6(13.2,-3.45)
  rect 2.5x2 smd mask+0.05: 5(17.25,0.75)
  round 0.5 hole 2 unplated mask+0.1: MT1(5,0) MT2(12,0)
  Multi-Layer keep-out circle w0.01: c12,0 r1.25
  Multi-Layer keep-out circle w0.01: c5,0 r1.25
  silkscreen extent -0.9,-3.7 16,3, body extent -0.9,-3 16,3, height 5
CON_SAMTEC_CLM-120-02-L-D_Reverse-to-Camera [mm] "not in line with Samtec spec"
  rect 1.85x0.7 smd mask+0.05: 1(-1.275,9.5) 2(1.275,9.5) 3(-1.275,8.5) 4(1.275,8.5) 5(-1.275,7.5) 6(1.275,7.5) 7(-1.275,6.5) 8(1.275,6.5) 9(-1.275,5.5) 10(1.275,5.5) 11(-1.275,4.5) 12(1.275,4.5) 13(-1.275,3.5) 14(1.275,3.5) 15(-1.275,2.5) 16(1.275,2.5) 17(-1.275,1.5) 18(1.275,1.5) 19(-1.275,0.5) 20(1.275,0.5) 21(-1.275,-0.5) 22(1.275,-0.5) 23(-1.275,-1.5) 24(1.275,-1.5) 25(-1.275,-2.5) 26(1.275,-2.5) 27(-1.275,-3.5) 28(1.275,-3.5) 29(-1.275,-4.5) 30(1.275,-4.5) 31(-1.275,-5.5) 32(1.275,-5.5) 33(-1.275,-6.5) 34(1.275,-6.5) 35(-1.275,-7.5) 36(1.275,-7.5) 37(-1.275,-8.5) 38(1.275,-8.5) 39(-1.275,-9.5) 40(1.275,-9.5)
  round 6 hole 3.2 mask+0.1: 41(0,15.27) 42(0,-15.27)
  silkscreen extent -16.5,-19 6,21, body extent -16.5,-19 6,21, height 5.69
CON_SAMTEC_ERF8-010-050-S-DV-TR [mm]
  rect 0.5x1.1 smd mask+0.05: 1(3.6,2.25) 2(3.6,-2.25) 3(2.8,2.25) 4(2.8,-2.25) 5(2,2.25) 6(2,-2.25) 7(1.2,2.25) 8(1.2,-2.25) 9(0.4,2.25) 10(0.4,-2.25) 11(-0.4,2.25) 12(-0.4,-2.25) 13(-1.2,2.25) 14(-1.2,-2.25) 15(-2,2.25) 16(-2,-2.25) 17(-2.8,2.25) 18(-2.8,-2.25) 19(-3.6,2.25) 20(-3.6,-2.25)
  round 0 hole 1.5 unplated mask+0.1: NPTH1(5.4,-1.5) NPTH2(-5.4,-1.5)
  Multi-Layer keep-out circle w0.01: c-5.4,-1.5 r0.951
  Multi-Layer keep-out circle w0.01: c5.4,-1.5 r0.951
  silkscreen extent -7,-2.8 7,2.8, body extent -7,-2.8 7,2.8, height 5.3
CON_SAMTEC_FTR-120-53-L-D-LC [mm]
  rect 0.85x3.1 smd mask+0.05: 1(-12.065,-2.55) 2(-12.065,2.55) 3(-10.795,-2.55) 4(-10.795,2.55) 5(-9.525,-2.55) 6(-9.525,2.55) 7(-8.255,-2.55) 8(-8.255,2.55) 9(-6.985,-2.55) 10(-6.985,2.55) 11(-5.715,-2.55) 12(-5.715,2.55) 13(-4.445,-2.55) 14(-4.445,2.55) 15(-3.175,-2.55) 16(-3.175,2.55) 17(-1.905,-2.55) 18(-1.905,2.55) 19(-0.635,-2.55) 20(-0.635,2.55) 21(0.635,-2.55) 22(0.635,2.55) 23(1.905,-2.55) 24(1.905,2.55) 25(3.175,-2.55) 26(3.175,2.55) 27(4.445,-2.55) 28(4.445,2.55) 29(5.715,-2.55) 30(5.715,2.55) 31(6.985,-2.55) 32(6.985,2.55) 33(8.255,-2.55) 34(8.255,2.55) 35(9.525,-2.55) 36(9.525,2.55) 37(10.795,-2.55) 38(10.795,2.55) 39(12.065,-2.55) 40(12.065,2.55)
  round 0 hole 1.5 unplated mask+0.05: NPTH1(-11.43,0) NPTH2(11.43,0)
  silkscreen extent -12.7,-2.05 12.7,2.05, body extent -12.7,-3.76 12.7,3.76, height 11.05
CON_SAMTEC_FTR-130-53-L-D-LC [mm]
  rect 0.85x3.1 smd mask+0.05: 1(-18.415,-2.55) 2(-18.415,2.55) 3(-17.145,-2.55) 4(-17.145,2.55) 5(-15.875,-2.55) 6(-15.875,2.55) 7(-14.605,-2.55) 8(-14.605,2.55) 9(-13.335,-2.55) 10(-13.335,2.55) 11(-12.065,-2.55) 12(-12.065,2.55) 13(-10.795,-2.55) 14(-10.795,2.55) 15(-9.525,-2.55) 16(-9.525,2.55) 17(-8.255,-2.55) 18(-8.255,2.55) 19(-6.985,-2.55) 20(-6.985,2.55) 21(-5.715,-2.55) 22(-5.715,2.55) 23(-4.445,-2.55) 24(-4.445,2.55) 25(-3.175,-2.55) 26(-3.175,2.55) 27(-1.905,-2.55) 28(-1.905,2.55) 29(-0.635,-2.55) 30(-0.635,2.55) 31(0.635,-2.55) 32(0.635,2.55) 33(1.905,-2.55) 34(1.905,2.55) 35(3.175,-2.55) 36(3.175,2.55) 37(4.445,-2.55) 38(4.445,2.55) 39(5.715,-2.55) 40(5.715,2.55) 41(6.985,-2.55) 42(6.985,2.55) 43(8.255,-2.55) 44(8.255,2.55) 45(9.525,-2.55) 46(9.525,2.55) 47(10.795,-2.55) 48(10.795,2.55) 49(12.065,-2.55) 50(12.065,2.55) 51(13.335,-2.55) 52(13.335,2.55) 53(14.605,-2.55) 54(14.605,2.55) 55(15.875,-2.55) 56(15.875,2.55) 57(17.145,-2.55) 58(17.145,2.55) 59(18.415,-2.55) 60(18.415,2.55)
  round 0 hole 1.5 unplated mask+0.05: NPTH1(-17.78,0) NPTH2(17.78,0)
  silkscreen extent -19.05,-2.05 19.05,2.05, body extent -19.05,-3.76 19.05,3.76, height 11.05
CON_SAMTEC_FTSH-105-01-L-DV-K [mm]
  oval 0.74x2.79 smd mask+0.05: 1(-2.54,-2.035) 2(-2.54,2.035) 3(-1.27,-2.035) 4(-1.27,2.035) 5(0,-2.035) 6(0,2.035) 7(1.27,-2.035) 8(1.27,2.035) 9(2.54,-2.035) 10(2.54,2.035)
  round 0 hole 1 unplated paste-10 mask+0.05: NPTH1(-1.905,0) NPTH2(1.905,0)
  silkscreen extent -3.17,-2.54 3.17,2.54, body extent -3.17,-2.92 3.18,2.92, height 6.12
CON_SAMTEC_FTSH-110-01-L-DV [mm]
  rect 0.74x2.79 smd mask+0.05: 1(-5.715,-2.035) 2(-5.715,2.035) 3(-4.445,-2.035) 4(-4.445,2.035) 5(-3.175,-2.035) 6(-3.175,2.035) 7(-1.905,-2.035) 8(-1.905,2.035) 9(-0.635,-2.035) 10(-0.635,2.035) 11(0.635,-2.035) 12(0.635,2.035) 13(1.905,-2.035) 14(1.905,2.035) 15(3.175,-2.035) 16(3.175,2.035) 17(4.445,-2.035) 18(4.445,2.035) 19(5.715,-2.035) 20(5.715,2.035)
  silkscreen extent -6.35,-1.71 6.35,1.71, body extent -6.35,-2.92 6.35,2.92, height 5.97
CON_SAMTEC_SSM-104-L-DH [mm]
  rect 1.2x3.4 smd mask+0.05: 1(3.81,-5) 2(3.81,5) 3(1.27,-5) 4(1.27,5) 5(-1.27,-5) 6(-1.27,5) 7(-3.81,-5) 8(-3.81,5)
  silkscreen extent -5.08,-4.06 5.08,4.06, body extent -5.08,-5.46 5.1,5.46, height 5.92
CON_SAMTEC_TST-117-01-T-D [mm]
  rect 1.8x1.8 hole 1.1 mask+0.05: 1(-20.32,-1.27)
  round 1.8 hole 1.1 mask+0.05: 2(-20.32,1.27) 3(-17.78,-1.27) 4(-17.78,1.27) 5(-15.24,-1.27) 6(-15.24,1.27) 7(-12.7,-1.27) 8(-12.7,1.27) 9(-10.16,-1.27) 10(-10.16,1.27) 11(-7.62,-1.27) 12(-7.62,1.27) 13(-5.08,-1.27) 14(-5.08,1.27) 15(-2.54,-1.27) 16(-2.54,1.27) 17(0,-1.27) 18(0,1.27) 19(2.54,-1.27) 20(2.54,1.27) 21(5.08,-1.27) 22(5.08,1.27) 23(7.62,-1.27) 24(7.62,1.27) 25(10.16,-1.27) 26(10.16,1.27) 27(12.7,-1.27) 28(12.7,1.27) 29(15.24,-1.27) 30(15.24,1.27) 31(17.78,-1.27) 32(17.78,1.27) 33(20.32,-1.27) 34(20.32,1.27)
  silkscreen extent -25.4,-4.83 25.4,4.83, body extent -25.4,-4.83 25.4,4.83, height 9.27
CON_SAMTEC_TSW-102-07-G-S [mm]
  rect 1.85x1.85 / inner round 1.85 / far side rect 1.85x1.85 hole 1 mask+0.05: 1(-1.27,0)
  round 1.85 hole 1 mask+0.05: 2(1.27,0)
  silkscreen extent -2.58,-1.3 2.58,1.3, body extent -2.67,-1.3 2.58,1.3, height 8.38
CON_SAMTEC_TSW-103-07-F-S [mm]
  rect 1.85x1.85 / inner round 1.85 / far side rect 1.85x1.85 hole 1 mask+0.05: 1(-2.54,0)
  round 1.85 hole 1 mask+0.05: 2(0,0) 3(2.54,0)
  silkscreen extent -3.85,-1.3 3.85,1.3, body extent -3.91,-1.37 3.91,1.37, height 8.38
CON_SAMTEC_TSW-104-07-G-S [mm]
  rect 1.85x1.85 / inner round 1.85 / far side rect 1.85x1.85 hole 1 mask+0.05: 1(-3.81,0)
  round 1.85 hole 1 mask+0.05: 2(-1.27,0) 3(1.27,0) 4(3.81,0)
  silkscreen extent -5.12,-1.3 5.12,1.3, body extent -5.21,-1.37 5.18,1.37, height 8.38
CON_SAMTEC_TSW-106-07-X-D [mm]
  rect 1.85x1.85 / inner round 1.85 / far side rect 1.85x1.85 hole 1 mask+0.05: 1(-6.35,-1.27)
  round 1.85 hole 1 mask+0.05: 2(-6.35,1.27) 3(-3.81,-1.27) 4(-3.81,1.27) 5(-1.27,-1.27) 6(-1.27,1.27) 7(1.27,-1.27) 8(1.27,1.27) 9(3.81,-1.27) 10(3.81,1.27) 11(6.35,-1.27) 12(6.35,1.27)
  silkscreen extent -7.62,-2.54 7.62,2.54, body extent -7.62,-2.55 7.62,2.54, height 8.38
CON_STDC14_Receiver_MEDIUM_WITH_MIPI10_3D [mm] "compatible with FTSH-105-01-L-DV,-K and FTSH-107-01-L-DV,-K,-A,-P,-ES"
  round 0 hole 1.19 unplated mask+0.05: 0(-5.445,0) 0(5.445,0)
  round 0 hole 0.97 unplated mask+0.05: 0(-3.175,0) 0(3.175,0)
  rect 0.74x2.79 smd mask+0.05: 1(-3.81,-2.032) 2(-3.81,2.032) 3(-2.54,-2.032) 4(-2.54,2.032) 5(-1.27,-2.032) 6(-1.27,2.032) 7(0,-2.032) 8(0,2.032) 9(1.27,-2.032) 10(1.27,2.032) 11(2.54,-2.032) 12(2.54,2.032) 13(3.81,-2.032) 14(3.81,2.032)
  silkscreen extent -6.3,-4.38 6.3,3.6, body extent -6.3,-2.92 6.3,2.92, height 6.6
CON_USBMICROAB_MOLEX_47590-0001_H3 [mm]
  rect 0.4x1.35 smd mask+0.05: 1(1.3,4.125) 2(0.65,4.125) 3(0,4.125) 4(-0.65,4.125) 5(-1.3,4.125)
  oval 1.05x1.25 hole 0.65 slot 0.85 at 90 deg mask+0.05: 6(-2.225,4.45) 7(2.225,4.45)
  rrect50% 1.375x1.9 hole 0.6 slot 1.3 at 90 deg copper offset 0.188,0 mask+0.05: 8(-4.175,1.45)
  rrect50% 1.375x1.9 hole 0.6 slot 1.3 at 90 deg copper offset -0.188,0 mask+0.05: 9(4.175,1.45)
  rect 2.9x1.9 smd mask+0.05: 10(0,1.45)
  oval 0.85x2.425 hole 0.85 slot 2.425 at 90 deg unplated mask+0.1: 11(-2.375,0.8) 12(2.375,0.8)
  silkscreen extent -4.1,-1.3 4.1,4.3, body extent -4.32,-1.36 4.33,4.6, height 3
CON_USBMICROB_MOLEX_105017-0001_H2P90 [mm]
  rect 0.4x1.35 smd mask+0.05: 1(-1.3,4.15) 2(-0.65,4.15) 3(0,4.15) 4(0.65,4.15) 5(1.3,4.15)
  round 1.5 hole 0.9 mask+0.05: 6(-2.5,4.15) 7(2.5,4.15)
  oval 1.2x1.9 hole 0.6 slot 1.3 at 90 deg mask+0.05: 8(3.5,1.45) 9(-3.5,1.45)
  rect 1.5x1.9 smd mask+0.05: 10(-1,1.45) 11(1,1.45)
  Top Layer region: 2.3,2.4 3.5,2.4 3.5,0.5 2.3,0.5 2.3,2.4
  Top Layer region: -3.5,2.4 -2.3,2.4 -2.3,0.5 -3.5,0.5 -3.5,2.4
  silkscreen extent -4,-0.7 4,4.6, body extent -4.1,-1.15 4.1,4.66, height 2.9
CPOL_TAJ-A_1206_H180 [mm]
  rect 1.45x1.6 smd mask+0.05: 1(-1.175,0) 2(1.175,0)
  silkscreen extent -2.15,-1.05 1.7,1.05, body extent -1.7,-0.9 1.7,0.9, height 1.8
CPOL_TAJ-C_2312_H2P6 [mm]
  rect 2.2x2.6 smd mask+0.05: 1(-2.3,0) 2(2.3,0)
  silkscreen extent -3.6,-1.85 3.1,1.85, body extent -3.1,-1.7 3.1,1.7, height 2.8
CRY_NX2016SA_4P [mm]
  rect 0.85x0.75 smd mask+0.05: 1(-0.675,-0.525) 2(0.675,-0.525) 3(0.675,0.525) 4(-0.675,0.525)
  silkscreen extent -1.22,-1.02 1.05,0.85, body extent -1.05,-0.85 1.05,0.85, height 0.7
CRY_NX3215SA_2P [mm]
  rect 1x1.8 smd mask+0.05: 1(-1.25,0) 2(1.25,0)
  silkscreen extent -0.63,-0.8 0.63,0.8, body extent -1.65,-0.8 1.65,0.8, height 0.9
DIO_SOD323 [mm]
  rect 1.06x0.54 smd mask+0.05: 1(-1.07,0) 2(1.07,0)
  silkscreen extent -0.9,-0.72 0.9,0.72, body extent -1.3,-0.78 1.3,0.78, height 1.17
DIO_SOT323 [mm]
  rect 0.5x0.95 smd mask+0.05: 1(-0.65,-0.975) 2(0.65,-0.975) 3(0,0.975)
  silkscreen extent -1.15,-0.67 1.15,0.67, body extent -1.15,-1.12 1.15,1.12, height 1.1
DIOZ_LITTELFUSE_ZEN056V130A24LS [mm]
  rect 0.56x2.21 smd mask+0.05: 1(-1.72,0)
  rect 0.56x0.94 smd mask+0.05: 2(1.72,0.635) 3(1.72,-0.635)
  silkscreen extent -2.12,-2.07 2.12,2.07, body extent -2.12,-2.07 2.12,2.07, height 2
ESD_FLIP-CHIP-BGA8_1P9X0P9_P050 [mm] "IPC"
  round 0.2 smd paste+0 mask+0.05: 1(-0.75,-0.25) 2(-0.25,-0.25) 3(0.25,-0.25) 4(0.75,-0.25) 5(0.75,0.25) 6(0.25,0.25) 7(-0.25,0.25) 8(-0.75,0.25)
  silkscreen extent -1.17,-0.67 1.02,0.53, body extent -0.97,-0.48 0.97,0.48, height 0.64
ESD_QFN2_1P6X1_P125 [mm]
  rect 0.55x0.8 smd mask+0.05: 1(-0.625,0) 2(0.625,0)
  silkscreen extent -1,-0.55 0.85,0.55, body extent -0.85,-0.55 0.85,0.55, height 0.61
ESD_QFN-6L_1P7X1P5_P050 [mm]
  rect 0.25x0.6 smd mask+0.05: 1(-0.5,-0.65) 2(0,-0.65) 3(0.5,-0.65) 4(0.5,0.65) 5(0,0.65) 6(-0.5,0.65)
  silkscreen extent -0.9,-0.8 0.9,0.8, body extent -0.9,-0.8 0.9,0.8, height 0.56
ESD_SOT23-6L [mm]
  rect 0.6x1.2 smd mask+0.05: 1(-0.95,-1.15) 2(0,-1.15) 3(0.95,-1.15) 4(0.95,1.15) 5(0,1.15) 6(-0.95,1.15)
  silkscreen extent -1.53,-0.87 1.53,0.87, body extent -1.52,-1.5 1.52,1.5, height 1.45
ESD_SOT323-5L [mm]
  rect 0.4x1.2 smd mask+0.05: 1(-0.65,-0.85) 2(0,-0.85) 3(0.65,-0.85) 4(0.65,0.85) 5(-0.65,0.85)
  silkscreen extent -1.22,-1.21 1.22,0.77, body extent -1.15,-1.05 1.15,1.05, height 1.1
ESD_ST0201 [mm]
  rect 0.425x0.33 smd mask+0.05: 1(-0.312,0) 2(0.312,0)
  silkscreen extent -0.55,-0.3 0.33,0.3, body extent -0.34,-0.18 0.34,0.18, height 0.34
ESD_UQFN-10L_2P5X1_P050 [mm]
  rect 0.2x0.58 smd mask+0.05: 1(-1,-0.41) 2(-0.5,-0.41) 4(0.5,-0.41) 5(1,-0.41) 6(1,0.41) 7(0.5,0.41) 9(-0.5,0.41) 10(-1,0.41)
  rect 0.4x0.58 smd mask+0.05: 3(0,-0.41) 8(0,0.41)
  silkscreen extent -1.38,-0.63 1.38,0.63, body extent -1.3,-0.55 1.3,0.55, height 0.51
FIL_MURATA_BNX002-01 [mm]
  round 1.7 hole 1.2 mask+0.05: 1(2.5,2.5) 2(2.5,-2.5) 3(-2.5,2.5) 4(-2.5,-2.5) 5(0,0) 6(5,0)
  silkscreen extent -6.24,-5.75 6.26,5.75, body extent -6.25,-5.75 6.25,5.75, height 13
ICC_BGA24_5X5-BALL-ARRAY_6X8_P1 [mm]
  round 0.45 smd mask+0.05: A2(-1,2) A3(0,2) A4(1,2) A5(2,2) B1(-2,1) B2(-1,1) B3(0,1) B4(1,1) B5(2,1) C1(-2,0) C2(-1,0) C3(0,0) C4(1,0) C5(2,0) D1(-2,-1) D2(-1,-1) D3(0,-1) D4(1,-1) D5(2,-1) E1(-2,-2) E2(-1,-2) E3(0,-2) E4(1,-2) E5(2,-2)
  silkscreen extent -3.05,-4.05 3.05,4.05, body extent -3.05,-4.05 3.05,4.05, height 1.2
ICC_DFN6-EPAD_3X3_P095 [mm]
  rect 0.45x0.5 smd mask+0.05: 1(-0.95,-1.3) 2(0,-1.3) 3(0.95,-1.3) 4(0.95,1.3) 5(0,1.3) 6(-0.95,1.3)
  rect 2.5x1.7 smd mask+0.05: EP(0,0)
  silkscreen extent -1.55,-1.55 1.55,1.55, body extent -1.55,-1.55 1.55,1.55, height 1
ICC_FBGA64_11X13_P1 [mm] "IPC"
  round 0.45 smd mask+0.05: A1(-3.5,3.5) A2(-2.5,3.5) A3(-1.5,3.5) A4(-0.5,3.5) A5(0.5,3.5) A6(1.5,3.5) A7(2.5,3.5) A8(3.5,3.5) B1(-3.5,2.5) B2(-2.5,2.5) B3(-1.5,2.5) B4(-0.5,2.5) B5(0.5,2.5) B6(1.5,2.5) B7(2.5,2.5) B8(3.5,2.5) C1(-3.5,1.5) C2(-2.5,1.5) C3(-1.5,1.5) C4(-0.5,1.5) C5(0.5,1.5) C6(1.5,1.5) C7(2.5,1.5) C8(3.5,1.5) D1(-3.5,0.5) D2(-2.5,0.5) D3(-1.5,0.5) D4(-0.5,0.5) D5(0.5,0.5) D6(1.5,0.5) D7(2.5,0.5) D8(3.5,0.5) E1(-3.5,-0.5) E2(-2.5,-0.5) E3(-1.5,-0.5) E4(-0.5,-0.5) E5(0.5,-0.5) E6(1.5,-0.5) E7(2.5,-0.5) E8(3.5,-0.5) F1(-3.5,-1.5) F2(-2.5,-1.5) F3(-1.5,-1.5) F4(-0.5,-1.5) F5(0.5,-1.5) F6(1.5,-1.5) F7(2.5,-1.5) F8(3.5,-1.5) G1(-3.5,-2.5) G2(-2.5,-2.5) G3(-1.5,-2.5) G4(-0.5,-2.5) G5(0.5,-2.5) G6(1.5,-2.5) G7(2.5,-2.5) G8(3.5,-2.5) H1(-3.5,-3.5) H2(-2.5,-3.5) H3(-1.5,-3.5) H4(-0.5,-3.5) H5(0.5,-3.5) H6(1.5,-3.5) H7(2.5,-3.5) H8(3.5,-3.5)
  silkscreen extent -5.7,-6.55 5.55,6.7, body extent -5.55,-6.55 5.55,6.55, height 1.41
ICC_LQFP48_7X7_P050 [mm]
  rect 0.3x1.2 smd mask+0.05: 1(-2.75,-4.25) 2(-2.25,-4.25) 3(-1.75,-4.25) 4(-1.25,-4.25) 5(-0.75,-4.25) 6(-0.25,-4.25) 7(0.25,-4.25) 8(0.75,-4.25) 9(1.25,-4.25) 10(1.75,-4.25) 11(2.25,-4.25) 12(2.75,-4.25) 25(2.75,4.25) 26(2.25,4.25) 27(1.75,4.25) 28(1.25,4.25) 29(0.75,4.25) 30(0.25,4.25) 31(-0.25,4.25) 32(-0.75,4.25) 33(-1.25,4.25) 34(-1.75,4.25) 35(-2.25,4.25) 36(-2.75,4.25)
  rect 1.2x0.3 smd mask+0.05: 13(4.25,-2.75) 14(4.25,-2.25) 15(4.25,-1.75) 16(4.25,-1.25) 17(4.25,-0.75) 18(4.25,-0.25) 19(4.25,0.25) 20(4.25,0.75) 21(4.25,1.25) 22(4.25,1.75) 23(4.25,2.25) 24(4.25,2.75) 37(-4.25,2.75) 38(-4.25,2.25) 39(-4.25,1.75) 40(-4.25,1.25) 41(-4.25,0.75) 42(-4.25,0.25) 43(-4.25,-0.25) 44(-4.25,-0.75) 45(-4.25,-1.25) 46(-4.25,-1.75) 47(-4.25,-2.25) 48(-4.25,-2.75)
  silkscreen extent -3.52,-3.52 3.52,3.52, body extent -4.5,-4.5 4.5,4.5, height 1.6
ICC_MINI-BGA48_9X11_P075 [mm] "IPC"
  round 0.28 smd mask+0.05: A1(-1.875,2.625) A2(-1.125,2.625) A3(-0.375,2.625) A4(0.375,2.625) A5(1.125,2.625) A6(1.875,2.625) B1(-1.875,1.875) B2(-1.125,1.875) B3(-0.375,1.875) B4(0.375,1.875) B5(1.125,1.875) B6(1.875,1.875) C1(-1.875,1.125) C2(-1.125,1.125) C3(-0.375,1.125) C4(0.375,1.125) C5(1.125,1.125) C6(1.875,1.125) D1(-1.875,0.375) D2(-1.125,0.375) D3(-0.375,0.375) D4(0.375,0.375) D5(1.125,0.375) D6(1.875,0.375) E1(-1.875,-0.375) E2(-1.125,-0.375) E3(-0.375,-0.375) E4(0.375,-0.375) E5(1.125,-0.375) E6(1.875,-0.375) F1(-1.875,-1.125) F2(-1.125,-1.125) F3(-0.375,-1.125) F4(0.375,-1.125) F5(1.125,-1.125) F6(1.875,-1.125) G1(-1.875,-1.875) G2(-1.125,-1.875) G3(-0.375,-1.875) G4(0.375,-1.875) G5(1.125,-1.875) G6(1.875,-1.875) H1(-1.875,-2.625) H2(-1.125,-2.625) H3(-0.375,-2.625) H4(0.375,-2.625) H5(1.125,-2.625) H6(1.875,-2.625)
  silkscreen extent -4.7,-5.55 4.55,5.7, body extent -4.55,-5.55 4.55,5.55, height 1.21
ICC_QFN16-EPAD_4X4_P065 [mm]
  rect 0.35x0.7 smd mask+0.05: 1(-0.975,-1.9) 2(-0.325,-1.9) 3(0.325,-1.9) 4(0.975,-1.9) 9(0.975,1.9) 10(0.325,1.9) 11(-0.325,1.9) 12(-0.975,1.9)
  rect 0.7x0.35 smd mask+0.05: 5(1.9,-0.975) 6(1.9,-0.325) 7(1.9,0.325) 8(1.9,0.975) 13(-1.9,0.975) 14(-1.9,0.325) 15(-1.9,-0.325) 16(-1.9,-0.975)
  rect 2.7x2.7 smd mask+0.05: 17(0,0)
  silkscreen extent -2.05,-2.05 2.05,2.05, body extent -2.08,-2.08 2.09,2.09, height 1
ICC_QFN32-EPAD_5X5_P050 [mm]
  oval 0.3x0.75 smd mask+0.05: 1(-1.75,-2.425) 2(-1.25,-2.425) 3(-0.75,-2.425) 4(-0.25,-2.425) 5(0.25,-2.425) 6(0.75,-2.425) 7(1.25,-2.425) 8(1.75,-2.425) 17(1.75,2.425) 18(1.25,2.425) 19(0.75,2.425) 20(0.25,2.425) 21(-0.25,2.425) 22(-0.75,2.425) 23(-1.25,2.425) 24(-1.75,2.425)
  oval 0.75x0.3 smd mask+0.05: 9(2.425,-1.75) 10(2.425,-1.25) 11(2.425,-0.75) 12(2.425,-0.25) 13(2.425,0.25) 14(2.425,0.75) 15(2.425,1.25) 16(2.425,1.75) 25(-2.425,1.75) 26(-2.425,1.25) 27(-2.425,0.75) 28(-2.425,0.25) 29(-2.425,-0.25) 30(-2.425,-0.75) 31(-2.425,-1.25) 32(-2.425,-1.75)
  rect 3.7x3.7 smd mask+0.05: 33(0,0)
  silkscreen extent -2.63,-2.63 2.63,2.63, body extent -2.55,-2.55 2.55,2.55, height 1
ICC_SO8_5X4_P127 [mm]
  rect 0.7x1.75 smd mask+0.05: 1(-1.905,-2.375) 2(-0.635,-2.375) 3(0.635,-2.375) 4(1.905,-2.375) 5(1.905,2.375) 6(0.635,2.375) 7(-0.635,2.375) 8(-1.905,2.375)
  silkscreen extent -2.73,-3.25 2.58,2, body extent -2.57,-3 2.57,3, height 1.75
ICC_SSOP28_10P2X5P3_P065 [mm]
  rect 0.45x1.9 smd mask+0.05: 1(-4.225,-3.45) 2(-3.575,-3.45) 3(-2.925,-3.45) 4(-2.275,-3.45) 5(-1.625,-3.45) 6(-0.975,-3.45) 7(-0.325,-3.45) 8(0.325,-3.45) 9(0.975,-3.45) 10(1.625,-3.45) 11(2.275,-3.45) 12(2.925,-3.45) 13(3.575,-3.45) 14(4.225,-3.45) 15(4.225,3.45) 16(3.575,3.45) 17(2.925,3.45) 18(2.275,3.45) 19(1.625,3.45) 20(0.975,3.45) 21(0.325,3.45) 22(-0.325,3.45) 23(-0.975,3.45) 24(-1.625,3.45) 25(-2.275,3.45) 26(-2.925,3.45) 27(-3.575,3.45) 28(-4.225,3.45)
  silkscreen extent -5.25,-2.8 5.25,2.8, body extent -5.25,-3.9 5.25,3.9, height 2
ICC_TFBGA90_8X13_P080 [mm] "IPC"
  round 0.35 smd mask+0.05: A1(-3.2,5.6) A2(-2.4,5.6) A3(-1.6,5.6) A7(1.6,5.6) A8(2.4,5.6) A9(3.2,5.6) B1(-3.2,4.8) B2(-2.4,4.8) B3(-1.6,4.8) B7(1.6,4.8) B8(2.4,4.8) B9(3.2,4.8) C1(-3.2,4) C2(-2.4,4) C3(-1.6,4) C7(1.6,4) C8(2.4,4) C9(3.2,4) D1(-3.2,3.2) D2(-2.4,3.2) D3(-1.6,3.2) D7(1.6,3.2) D8(2.4,3.2) D9(3.2,3.2) E1(-3.2,2.4) E2(-2.4,2.4) E3(-1.6,2.4) E7(1.6,2.4) E8(2.4,2.4) E9(3.2,2.4) F1(-3.2,1.6) F2(-2.4,1.6) F3(-1.6,1.6) F7(1.6,1.6) F8(2.4,1.6) F9(3.2,1.6) G1(-3.2,0.8) G2(-2.4,0.8) G3(-1.6,0.8) G7(1.6,0.8) G8(2.4,0.8) G9(3.2,0.8) H1(-3.2,0) H2(-2.4,0) H3(-1.6,0) H7(1.6,0) H8(2.4,0) H9(3.2,0) J1(-3.2,-0.8) J2(-2.4,-0.8) J3(-1.6,-0.8) J7(1.6,-0.8) J8(2.4,-0.8) J9(3.2,-0.8) K1(-3.2,-1.6) K2(-2.4,-1.6) K3(-1.6,-1.6) K7(1.6,-1.6) K8(2.4,-1.6) K9(3.2,-1.6) L1(-3.2,-2.4) L2(-2.4,-2.4) L3(-1.6,-2.4) L7(1.6,-2.4) L8(2.4,-2.4) L9(3.2,-2.4) M1(-3.2,-3.2) M2(-2.4,-3.2) M3(-1.6,-3.2) M7(1.6,-3.2) M8(2.4,-3.2) M9(3.2,-3.2) N1(-3.2,-4) N2(-2.4,-4) N3(-1.6,-4) N7(1.6,-4) N8(2.4,-4) N9(3.2,-4) P1(-3.2,-4.8) P2(-2.4,-4.8) P3(-1.6,-4.8) P7(1.6,-4.8) P8(2.4,-4.8) P9(3.2,-4.8) R1(-3.2,-5.6) R2(-2.4,-5.6) R3(-1.6,-5.6) R7(1.6,-5.6) R8(2.4,-5.6) R9(3.2,-5.6)
  silkscreen extent -4.2,-6.55 4.05,6.7, body extent -4.06,-6.55 4.05,6.55, height 1.21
